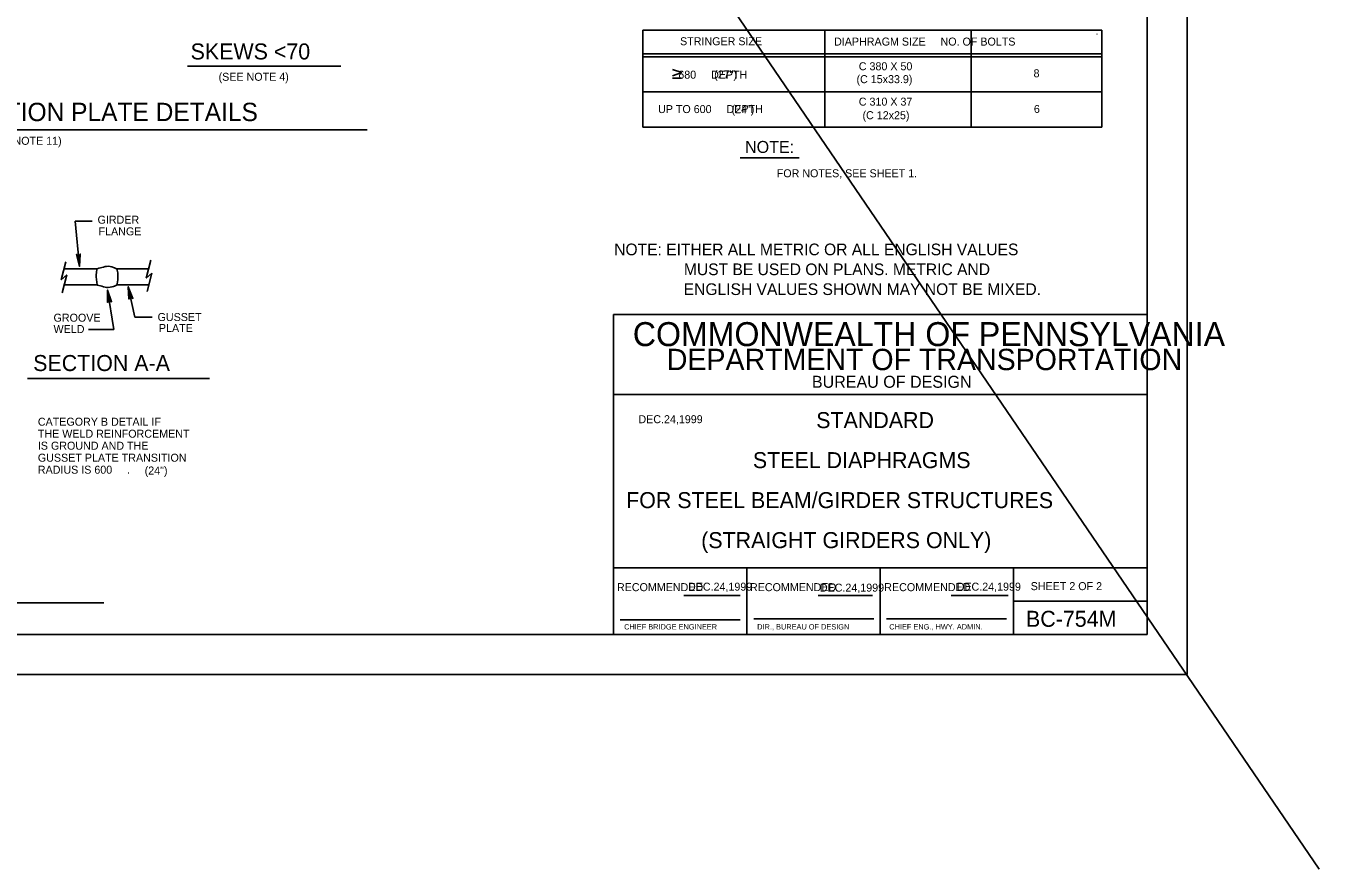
# Model space of a CAD drawing. Extents: x 634656 to 641360, y 298715 to 301183.
# Drawn here: x 640609.6 to 641094.4, y 298753.1 to 299069.3 of the extents above; entities that cross this region are included whole.
import ezdxf

# ---------------------------------------------------------------- set-up
doc = ezdxf.new("R2010")
doc.units = 0
for name, color, linetype in [('1', 7, 'Continuous'), ('2', 7, 'Continuous'), ('40', 7, 'Continuous')]:
    doc.layers.add(name, color=color, linetype=linetype)

msp = doc.modelspace()

# ---------------------------------------------------------------- linework, layer by layer
at = {"layer": '1'}
msp.add_line((640203.02, 300061.47), (641094.36, 298753.08), dxfattribs=at)
at = {"layer": '2'}
for p, q in [((641044.86, 299420.08), (641044.86, 298826.08)), ((641044.86, 299420.08), (641044.86, 298826.08)), ((641029.86, 299405.08), (641029.86, 298841.08)), ((641029.86, 299405.08), (641029.86, 298841.08)), ((640840.82, 299067.64), (640840.82, 299031.27)), ((640840.82, 299067.64), (641012.94, 299067.64)), ((640909.07, 299067.64), (640909.07, 299031.27)), ((640963.94, 299067.64), (640963.94, 299031.27)), ((641011.07, 299066.14), (641011.19, 299066.14)), ((641012.94, 299067.64), (641012.94, 299031.27)), ((640840.82, 299058.77), (641012.94, 299058.77)), ((640840.82, 299057.64), (641012.94, 299057.64)), ((640670.24, 299054.2), (640727.61, 299054.2)), ((640852.05, 299052.95), (640855.43, 299051.77)), ((640852.05, 299050.59), (640855.43, 299051.77)), ((640852, 299049.7), (640855.37, 299049.7)), ((640840.82, 299044.52), (641012.94, 299044.52)), ((640499.86, 299030.33), (640737.49, 299030.33)), ((640840.82, 299031.27), (641012.94, 299031.27)), ((640877.32, 299019.77), (640899.44, 299019.77)), ((640628.11, 298996.11), (640634.49, 298996.11)), ((640628.11, 298996.11), (640629.74, 298979.11)), ((640622.86, 298974.11), (640624.61, 298980.86)), ((640656.49, 298981.48), (640654.74, 298974.73)), ((640624.99, 298975.98), (640622.86, 298974.11)), ((640623.24, 298969.23), (640624.99, 298975.98)), ((640624.11, 298978.23), (640636.36, 298978.23)), ((640655.49, 298978.23), (640643.74, 298978.23)), ((640654.74, 298974.73), (640656.86, 298976.61)), ((640656.86, 298976.61), (640655.11, 298969.73)), ((640624.11, 298972.23), (640636.36, 298972.23)), ((640642.61, 298955.48), (640640.24, 298970.23)), ((640655.49, 298972.23), (640643.74, 298972.23)), ((640650.49, 298960.11), (640647.99, 298971.48)), ((640650.49, 298960.11), (640656.99, 298960.11)), ((640829.86, 298961.08), (640829.86, 298841.08)), ((640829.86, 298961.08), (640829.86, 298841.08)), ((641029.86, 298961.08), (640829.86, 298961.08)), ((641029.86, 298841.08), (641029.86, 298961.08)), ((641029.86, 298841.08), (641029.86, 298961.08)), ((640633.11, 298955.48), (640642.61, 298955.48)), ((640678.49, 298937.11), (640610.24, 298937.11)), ((641029.86, 298931.08), (640829.86, 298931.08)), ((641029.86, 298931.08), (640829.86, 298931.08)), ((641029.86, 298866.08), (640829.86, 298866.08)), ((641029.86, 298866.08), (640829.86, 298866.08)), ((640879.86, 298841.08), (640879.86, 298866.08)), ((640879.86, 298841.08), (640879.86, 298866.08)), ((640929.86, 298866.08), (640929.86, 298841.08)), ((640929.86, 298866.08), (640929.86, 298841.08)), ((640979.86, 298866.08), (640979.86, 298841.08)), ((640979.86, 298866.08), (640979.86, 298841.08)), ((640638.86, 298852.95), (640446.49, 298852.95)), ((640856.28, 298855.7), (640877.36, 298855.7)), ((640906.62, 298855.7), (640926.99, 298855.7)), ((640956.47, 298855.7), (640977.86, 298855.7)), ((640979.86, 298853.58), (641029.86, 298853.58)), ((640979.86, 298853.58), (641029.86, 298853.58)), ((640832.36, 298846.58), (640877.36, 298846.58)), ((640882.49, 298846.95), (640927.49, 298846.95)), ((640932.24, 298846.95), (640977.24, 298846.95)), ((641029.86, 298841.08), (640243.86, 298841.08)), ((641029.86, 298841.08), (640243.86, 298841.08)), ((640829.86, 298841.08), (641029.86, 298841.08)), ((640829.86, 298841.08), (641029.86, 298841.08)), ((640203.86, 298826.08), (641044.86, 298826.08)), ((640203.86, 298826.08), (641044.86, 298826.08))]:
    msp.add_line(p, q, dxfattribs=at)
for points in [[(640629.86, 298983.48), (640629.61, 298983.23), (640629.74, 298979.11), (640629.86, 298983.48), (640629.99, 298983.73), (640629.74, 298979.11), (640629.11, 298983.23), (640628.86, 298983.36), (640629.74, 298979.11), (640628.61, 298983.61), (640628.86, 298983.36)], [(640640.36, 298965.86), (640640.61, 298966.11), (640640.24, 298970.23), (640640.36, 298965.86), (640640.24, 298965.61), (640640.24, 298970.23), (640641.11, 298966.11), (640641.49, 298965.98), (640640.24, 298970.23), (640641.74, 298965.86), (640641.49, 298965.98)], [(640648.36, 298967.11), (640648.61, 298967.36), (640647.99, 298971.48), (640648.36, 298967.11), (640648.24, 298966.86), (640647.99, 298971.48), (640649.11, 298967.36), (640649.36, 298967.36), (640647.99, 298971.48), (640649.74, 298967.11), (640649.36, 298967.36)]]:
    msp.add_lwpolyline(points, dxfattribs=at)
for points in [[(640636.36, 298978.23), (640638.74, 298978.86), (640639.86, 298979.11), (640642.49, 298978.73), (640643.61, 298978.23)], [(640636.36, 298978.23), (640635.99, 298976.11), (640636.36, 298972.23)], [(640643.74, 298978.23), (640644.11, 298976.11), (640643.74, 298972.23)], [(640636.36, 298972.11), (640638.74, 298971.48), (640639.86, 298971.23), (640642.49, 298971.61), (640643.61, 298972.11)]]:
    msp.add_spline(points, degree=3, dxfattribs=at)

# ---------------------------------------------------------------- texts
for s, height, p in [('SKEWS <70', 6, (640671.36, 299056.7)), ('STRINGER SIZE', 3, (640854.82, 299062.02)), ('  DIAPHRAGM SIZE     NO. OF BOLTS', 3, (640910.32, 299061.9)), ('(SEE NOTE 4)', 3, (640681.86, 299048.7)), ('  680     DEPTH', 3, (640851.94, 299049.49)), ('C 380 X 50', 3, (640921.82, 299052.64)), ('8', 3, (640987.32, 299050.02)), ('C 310 X 37', 3, (640921.82, 299039.38)), ('DIAPHRAGM CONNECTION PLATE DETAILS', 6.8753, (640503.99, 299033.58)), ('UP TO 600     DEPTH', 3, (640846.57, 299036.59)), ('6', 3, (640987.44, 299036.63)), ('(SEE NOTE 11)', 3, (640594.49, 299024.7)), ('NOTE:', 4.5, (640879.19, 299021.64)), ('FOR NOTES, SEE SHEET 1.', 3, (640891.07, 299012.52)), ('GIRDER', 3, (640636.49, 298995.11)), ('FLANGE', 3, (640636.86, 298990.73)), ('GROOVE', 3, (640619.99, 298958.36)), ('GUSSET', 3, (640658.99, 298958.61)), ('WELD', 3, (640619.99, 298954.11)), ('PLATE', 3, (640659.49, 298954.48)), ('COMMONWEALTH OF PENNSYLVANIA', 9, (640837.11, 298949.2)), ('SECTION A-A', 6, (640612.36, 298939.86)), ('DEPARTMENT OF TRANSPORTATION', 8.0002, (640849.86, 298940.2)), ('BUREAU OF DESIGN', 4.5, (640904.24, 298933.58)), ('CATEGORY B DETAIL IF', 3, (640614.11, 298919.36)), ('DEC.24,1999', 3.0004, (640839.21, 298920.3)), ('STANDARD', 6, (640905.86, 298918.45)), ('THE WELD REINFORCEMENT', 3, (640614.11, 298914.86)), ('IS GROUND AND THE', 3, (640614.11, 298910.36)), ('GUSSET PLATE TRANSITION', 3, (640614.11, 298905.86)), ('STEEL DIAPHRAGMS', 6, (640882.11, 298903.45)), ('RADIUS IS 600     .', 3, (640614.11, 298901.36)), ('FOR STEEL BEAM/GIRDER STRUCTURES', 6, (640834.61, 298888.45)), ('(STRAIGHT GIRDERS ONLY)', 6, (640862.74, 298873.45)), ('RECOMMENDED', 3.0004, (640831.17, 298857.32)), ('DEC.24,1999', 3.0004, (640857.79, 298857.5)), ('RECOMMENDED', 3.0004, (640881.03, 298857.32)), ('DEC.24,1999', 3.0004, (640907.21, 298857.13)), ('RECOMMENDED', 3.0004, (640931.36, 298857.32)), ('DEC.24,1999', 3.0004, (640958.49, 298857.5)), ('SHEET 2 OF 2', 3, (640986.24, 298857.7)), ('BC-754M', 6, (640984.49, 298843.95)), ('CHIEF BRIDGE ENGINEER', 2.0002, (640833.86, 298842.95)), ('DIR., BUREAU OF DESIGN', 2.0002, (640883.74, 298842.95)), ('CHIEF ENG., HWY. ADMIN.', 2.0002, (640933.24, 298842.95))]:
    msp.add_text(s, height=height, dxfattribs=at).set_placement(p)
at = {"layer": '40'}
for s, height, p in [('(27")', 3, (640867.6, 299049.56)), ('(C 15x33.9)', 3, (640920.96, 299047.81)), ('(24")', 3, (640874.11, 299036.54)), ('(C 12x25)', 3, (640923.21, 299034.29)), ('NOTE: EITHER ALL METRIC OR ALL ENGLISH VALUES', 4.375, (640830.13, 298983.28)), ('MUST BE USED ON PLANS. METRIC AND', 4.375, (640856.26, 298975.82)), ('ENGLISH VALUES SHOWN MAY NOT BE MIXED.', 4.375, (640856.19, 298968.37)), ('(24")', 3, (640654.15, 298901.06))]:
    msp.add_text(s, height=height, dxfattribs=at).set_placement(p)

doc.saveas('drawing.dxf')
